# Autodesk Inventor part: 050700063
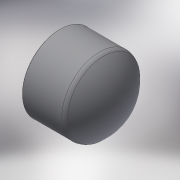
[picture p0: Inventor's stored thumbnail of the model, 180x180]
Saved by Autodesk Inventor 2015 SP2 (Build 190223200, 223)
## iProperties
Created: 2017-10
Part Number: 050700063
Material: Generic
Description: PLASSON CAP-CEMENT PVC 63
Document SubType Name: Modeling
Designer: KIM
Density: 1 g/cm^3
Appearance: Default
Author: KIM
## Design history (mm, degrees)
derived "050700.ipt"
feature "Solid1::050700.ipt"
tag "TaggingFeature1"
body "Solid1"
other parameters: "d7" = 0.63, "d9" = 73, "d28" = 1, "d29" = 38, "d30" = 63, "d31" = 56.7, "d32" = 57, "d33" = 39.9, "d34" = 6.3, "d_" = 63, "E_" = 73, "H_" = 57, "l_" = 38
